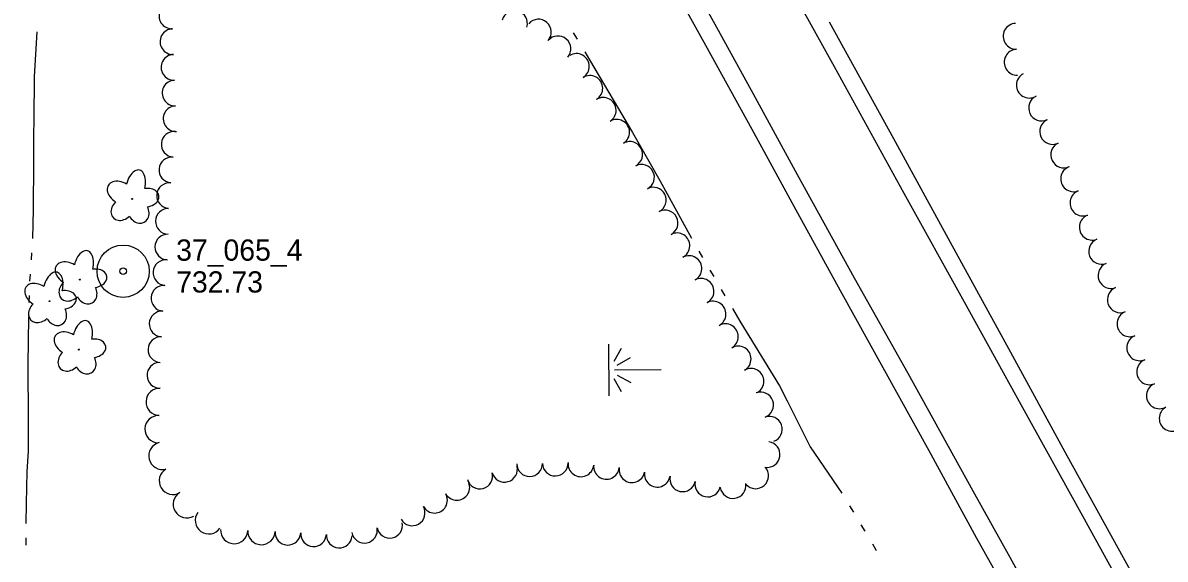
# Model space of a CAD drawing. Extents: x 589250 to 1188077, y 162953 to 363065.
# Drawn here: x 594446.7 to 594769.6, y 165591.2 to 165742.7 of the extents above; entities that cross this region are included whole.
import ezdxf

# ---------------------------------------------------------------- set-up
doc = ezdxf.new("R2010")
doc.units = 0
for name, color, linetype in [('E_LAND_TreeLine_P', 7, 'Continuous'), ('E_LAND_Vegetation', 7, 'Continuous'), ('E_MAP_PassPoints', 7, 'Continuous'), ('E_RDWY', 7, 'Continuous'), ('E_RDWY_Gravel', 7, 'Continuous'), ('E_WTR_FlowLine', 7, 'Continuous'), ('E_WTR_Wetland', 7, 'Continuous')]:
    doc.layers.add(name, color=color, linetype=linetype)

# ---------------------------------------------------------------- blocks, each defined once
blk = doc.blocks.new('POINT_DISPLAY')
blk.add_line((0, 0), (0, 0))

msp = doc.modelspace()

# ---------------------------------------------------------------- linework, layer by layer
at = {"layer": 'E_LAND_TreeLine_P'}
for centre, radius, start, end in [((594488.78, 165744.7), 3.63, 92.3493, 272.3493), ((594585.67, 165742.55), 3.63, 344.2474, 164.2474), ((594592.42, 165740.13), 3.63, 319.3629, 139.3629), ((594489.08, 165737.44), 3.63, 92.3493, 272.3493), ((594727.47, 165738.93), 3.66, 92.2893, 272.2893), ((594597.94, 165735.4), 3.63, 319.3629, 139.3629), ((594489.38, 165730.18), 3.63, 92.3493, 272.3493), ((594603.17, 165730.43), 3.63, 301.4514, 121.4514), ((594727.76, 165731.61), 3.66, 92.2893, 272.2893), ((594606.97, 165724.23), 3.63, 301.4514, 121.4514), ((594731.22, 165725.15), 3.66, 118.3303, 298.3303), ((594489.68, 165722.91), 3.63, 92.3493, 272.3493), ((594610.76, 165718.02), 3.63, 301.4514, 121.4514), ((594734.68, 165718.7), 3.66, 115.2366, 295.2366), ((594489.97, 165715.65), 3.63, 92.3493, 272.3493), ((594614.55, 165711.82), 3.63, 301.4514, 121.4514), ((594737.8, 165712.07), 3.66, 115.2366, 295.2366), ((594489.44, 165708.41), 3.63, 84.818, 264.818), ((594618.25, 165705.57), 3.63, 297.275, 117.275), ((594740.93, 165705.44), 3.66, 115.2366, 295.2366), ((594488.78, 165701.17), 3.63, 84.818, 264.818), ((594621.58, 165699.11), 3.63, 297.275, 117.275), ((594743.74, 165698.68), 3.66, 111.0828, 291.0828), ((594488.13, 165693.93), 3.63, 84.818, 264.818), ((594624.91, 165692.65), 3.63, 297.275, 117.275), ((594746.37, 165691.85), 3.66, 111.0828, 291.0828), ((594487.78, 165686.68), 3.63, 88.8961, 268.8961), ((594628.24, 165686.19), 3.63, 297.275, 117.275), ((594749.01, 165685.01), 3.66, 111.0828, 291.0828), ((594487.64, 165679.41), 3.63, 88.8961, 268.8961), ((594631.59, 165679.74), 3.63, 297.9151, 117.9151), ((594751.65, 165678.18), 3.66, 111.1262, 291.1262), ((594487.12, 165672.16), 3.63, 85.4255, 265.4255), ((594634.99, 165673.31), 3.63, 297.9151, 117.9151), ((594754.29, 165671.34), 3.66, 111.1262, 291.1262), ((594638.4, 165666.89), 3.63, 297.9151, 117.9151), ((594486.54, 165664.91), 3.63, 85.4255, 265.4255), ((594756.93, 165664.51), 3.66, 111.1262, 291.1262), ((594641.8, 165660.47), 3.63, 297.9151, 117.9151), ((594486.02, 165657.66), 3.63, 87.3592, 267.3592), ((594759.65, 165657.71), 3.66, 112.3158, 292.3158), ((594645.29, 165654.09), 3.63, 299.8323, 119.8323), ((594485.68, 165650.4), 3.63, 87.3592, 267.3592), ((594762.43, 165650.93), 3.66, 112.3158, 292.3158), ((594648.91, 165647.79), 3.63, 299.8323, 119.8323), ((594485.39, 165643.14), 3.63, 91.3501, 271.3501), ((594765.21, 165644.15), 3.66, 112.3158, 292.3158), ((594652.52, 165641.48), 3.63, 299.8323, 119.8323), ((594767.99, 165637.38), 3.66, 112.3158, 292.3158), ((594485.33, 165635.66), 3.86, 87.7738, 267.7738), ((594655.25, 165634.76), 3.63, 289.785, 109.785), ((594771.59, 165630.99), 3.66, 119.6081, 299.6081), ((594485.03, 165627.95), 3.86, 87.7738, 267.7738), ((594657.71, 165627.92), 3.63, 289.785, 109.785), ((594486.13, 165620.4), 3.86, 104.5227, 284.5227), ((594657.08, 165620.76), 3.63, 262.0568, 82.0568), ((594582.85, 165616.61), 3.63, 195.3863, 15.3863), ((594589.91, 165618.19), 3.63, 181.3501, 1.3501), ((594597.18, 165618.36), 3.63, 181.3501, 1.3501), ((594604.43, 165618.14), 3.63, 174.3122, 354.3122), ((594611.66, 165617.42), 3.63, 174.3122, 354.3122), ((594489.07, 165613.35), 3.86, 120.6601, 300.6601), ((594575.84, 165614.68), 3.63, 195.3863, 15.3863), ((594618.86, 165616.47), 3.63, 169.923, 349.923), ((594626.02, 165615.2), 3.63, 169.923, 349.923), ((594633.18, 165613.92), 3.63, 168.1595, 348.1595), ((594653.83, 165614.75), 3.63, 222.1137, 42.1137), ((594569.36, 165611.48), 3.63, 209.7431, 29.7431), ((594640.29, 165612.43), 3.63, 168.1595, 348.1595), ((594647.43, 165612), 3.63, 188.6559, 8.6559), ((594493, 165606.71), 3.86, 120.6601, 300.6601), ((594563.05, 165607.87), 3.63, 209.7431, 29.7431), ((594556.73, 165604.29), 3.63, 209.4738, 29.4738), ((594499.24, 165602.21), 3.86, 144.743, 324.743), ((594550.37, 165600.81), 3.63, 191.1562, 11.1562), ((594506.4, 165599.44), 3.86, 177.9339, 357.9339), ((594514.1, 165599.16), 3.86, 177.9339, 357.9339), ((594521.59, 165598.82), 3.63, 176.8213, 356.8213), ((594528.84, 165598.42), 3.63, 176.8213, 356.8213), ((594536.1, 165598.02), 3.63, 176.8213, 356.8213), ((594543.23, 165599.4), 3.63, 191.1562, 11.1562)]:
    msp.add_arc(centre, radius, start, end, dxfattribs=at)
at = {"layer": 'E_LAND_Vegetation'}
for centre in [(594477.52, 165692.99), (594462.8, 165670.2), (594454.2, 165664.11), (594462.52, 165650.41)]:
    msp.add_circle(centre, 0.128, dxfattribs=at)
for centre, major_axis, ratio in [((594478.53, 165696.52), (-1.11, -4.62), 0.560249), ((594474.41, 165694.66), (3.58, -2.24), 0.691916), ((594481.51, 165693.34), (-3.59, -0.54), 0.716896), ((594474.83, 165690.15), (2.59, 2.52), 0.782863), ((594479.35, 165689.45), (-1.59, 3.06), 0.832022), ((594459.69, 165671.87), (3.58, -2.24), 0.691916), ((594463.81, 165673.74), (-1.11, -4.62), 0.560249), ((594455.21, 165667.65), (-1.11, -4.62), 0.560249), ((594466.8, 165670.56), (-3.59, -0.54), 0.716896), ((594451.09, 165665.78), (3.58, -2.24), 0.691916), ((594460.11, 165667.37), (2.59, 2.52), 0.782863), ((594458.19, 165664.47), (-3.59, -0.54), 0.716896), ((594464.63, 165666.66), (-1.59, 3.06), 0.832022), ((594451.51, 165661.28), (2.59, 2.52), 0.782863), ((594456.03, 165660.57), (-1.59, 3.06), 0.832022), ((594463.53, 165653.95), (-1.11, -4.62), 0.560249), ((594459.41, 165652.09), (3.58, -2.24), 0.691916), ((594466.51, 165650.77), (-3.59, -0.54), 0.716896), ((594459.83, 165647.58), (2.59, 2.52), 0.782863), ((594464.35, 165646.88), (-1.59, 3.06), 0.832022)]:
    msp.add_ellipse(centre, major_axis=major_axis, ratio=ratio, start_param=1.570796, end_param=4.712389, dxfattribs=at)
at = {"layer": 'E_MAP_PassPoints'}
for radius in [7.38, 0.945]:
    msp.add_circle((594475, 165672.56), radius, dxfattribs=at)
at = {"layer": 'E_RDWY'}
for p, q in [((594643.36, 165740.55), (594632.2, 165760.84)), ((594661.39, 165756.88), (594676.02, 165730.38)), ((594653.2, 165722.63), (594643.36, 165740.55)), ((594676.02, 165730.38), (594695.74, 165694.59)), ((594665.66, 165699.83), (594653.2, 165722.63)), ((594681.82, 165670.59), (594665.66, 165699.83)), ((594695.74, 165694.59), (594712.77, 165663.93)), ((594696.91, 165643.64), (594681.82, 165670.59)), ((594712.77, 165663.93), (594728.82, 165634.89)), ((594715.34, 165610.39), (594696.91, 165643.64)), ((594728.82, 165634.89), (594746.24, 165603.44)), ((594725.76, 165591.69), (594715.34, 165610.39)), ((594746.24, 165603.44), (594765.9, 165567.84)), ((594738.76, 165568.19), (594725.76, 165591.69))]:
    msp.add_line(p, q, dxfattribs=at)
at = {"layer": 'E_RDWY_Gravel'}
for p, q in [((594639.74, 165736.37), (594624.67, 165763.44)), ((594674.63, 165743.02), (594692.78, 165710.11)), ((594652.86, 165712.57), (594639.74, 165736.37)), ((594664.71, 165690.89), (594652.86, 165712.57)), ((594692.78, 165710.11), (594708.86, 165680.73)), ((594677.83, 165667.06), (594664.71, 165690.89)), ((594708.86, 165680.73), (594725.35, 165650.72)), ((594689.92, 165645.29), (594677.83, 165667.06)), ((594725.35, 165650.72), (594741.8, 165620.54)), ((594702.91, 165621.81), (594689.92, 165645.29)), ((594716.28, 165597.22), (594702.91, 165621.81)), ((594741.8, 165620.54), (594759.68, 165588.08)), ((594728.64, 165575.19), (594716.28, 165597.22))]:
    msp.add_line(p, q, dxfattribs=at)
at = {"layer": 'E_WTR_FlowLine'}
for p, q in [((594450.57, 165740.23), (594449.87, 165727.45)), ((594602.26, 165739.96), (594603.35, 165738.17)), ((594605.51, 165734.58), (594606.9, 165732.29)), ((594606.9, 165732.29), (594618.99, 165711.78)), ((594449.87, 165727.45), (594449.73, 165715.35)), ((594449.73, 165715.35), (594449.69, 165711.04)), ((594618.99, 165711.78), (594620.91, 165708.42)), ((594449.69, 165711.04), (594449.63, 165703.42)), ((594620.91, 165708.42), (594626.77, 165698.18)), ((594449.63, 165703.42), (594449.6, 165690)), ((594626.77, 165698.18), (594635.7, 165681.91)), ((594449.6, 165690), (594449.34, 165681.82)), ((594449.1, 165677.8), (594448.97, 165675.79)), ((594637.73, 165678.25), (594638.79, 165676.44)), ((594640.91, 165672.83), (594641.97, 165671.03)), ((594448.7, 165671.76), (594448.57, 165669.75)), ((594644.1, 165667.42), (594645.16, 165665.62)), ((594448.42, 165665.73), (594448.35, 165663.71)), ((594448.21, 165659.48), (594448.06, 165646.2)), ((594448.22, 165659.68), (594448.21, 165659.48)), ((594647.28, 165662.01), (594649.36, 165658.47)), ((594649.36, 165658.47), (594660.62, 165640.23)), ((594448.06, 165646.2), (594448.16, 165630.47)), ((594660.62, 165640.23), (594662.77, 165635.92)), ((594662.77, 165635.92), (594669.26, 165622.91)), ((594448.16, 165630.46), (594448.17, 165629.43)), ((594448.17, 165629.43), (594448.12, 165621.69)), ((594448.12, 165621.69), (594447.82, 165616)), ((594669.26, 165622.91), (594678.19, 165609.85)), ((594447.82, 165616), (594447.57, 165606.96)), ((594447.57, 165606.96), (594447.52, 165601.26)), ((594680.4, 165606.29), (594681.47, 165604.49)), ((594683.61, 165600.9), (594684.69, 165599.1)), ((594447.48, 165597.23), (594447.49, 165595.21)), ((594686.83, 165595.51), (594687.83, 165593.83)), ((594687.83, 165593.83), (594687.9, 165593.7))]:
    msp.add_line(p, q, dxfattribs=at)
at = {"layer": 'E_WTR_Wetland'}
for p, q in [((594612.24, 165651.92), (594612.37, 165637.36)), ((594615.77, 165650.7), (594613.75, 165647.06)), ((594614.67, 165645.99), (594618.44, 165648.19)), ((594627.13, 165644.75), (594613.93, 165644.63)), ((594615.88, 165638.53), (594613.79, 165642.13)), ((594614.7, 165643.23), (594618.51, 165641.1))]:
    msp.add_line(p, q, dxfattribs=at)

# ---------------------------------------------------------------- block references
at = {"layer": 'E_WTR_Wetland', "rotation": 89.47202838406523}
for p in [(594612.3, 165645.08), (594612.31, 165644.59), (594612.31, 165644.53), (594613.93, 165644.63), (594615.19, 165644.64)]:
    msp.add_blockref('POINT_DISPLAY', p, dxfattribs=at)

# ---------------------------------------------------------------- texts
at = {"layer": 'E_MAP_PassPoints'}
for s, p in [('37_065_4', (594490, 165675.54)), ('732.73', (594490, 165666.54))]:
    msp.add_text(s, height=6, dxfattribs=at).set_placement(p)

doc.saveas('drawing.dxf')
